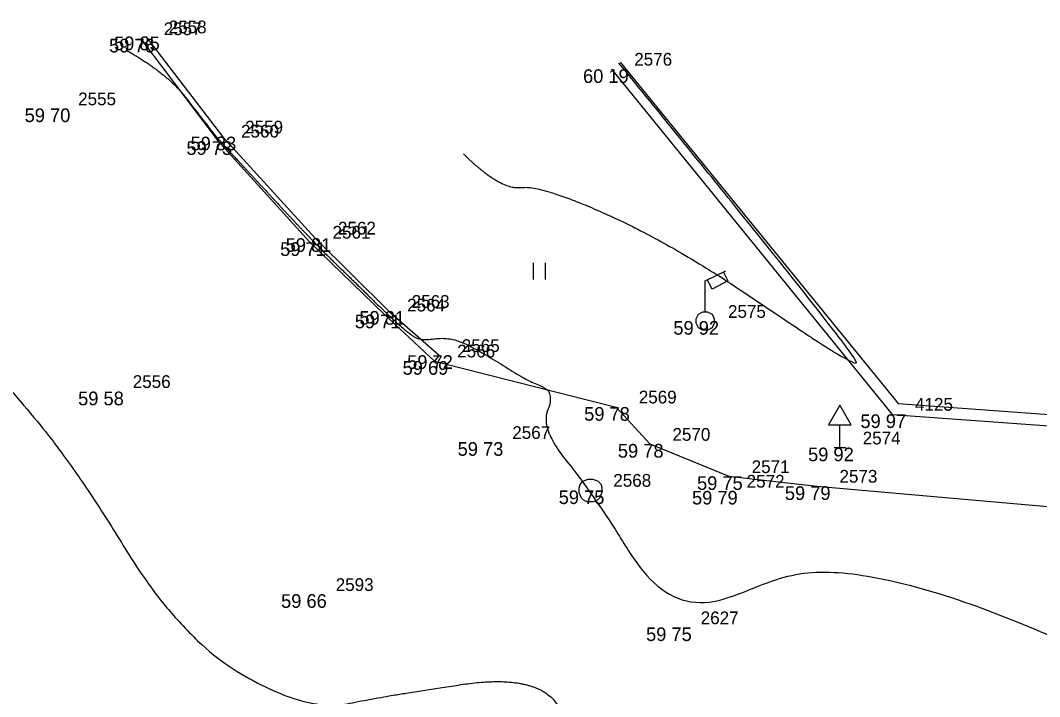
# Model space of a CAD drawing. Extents: x -704017 to -701500, y -1008977 to -1008450.
# Drawn here: x -702593.72 to -702571.32, y -1008762.02 to -1008747.17 of the extents above; entities that cross this region are included whole.
import ezdxf

# ---------------------------------------------------------------- set-up
doc = ezdxf.new("R2010")
doc.units = 0
for name, color, linetype in [('Z_body', 7, 'Continuous'), ('Z_body_cisla', 7, 'Continuous'), ('Z_body_vysky', 7, 'Continuous'), ('Z_dopravni_znaceni', 7, 'Continuous'), ('Z_komunikace', 7, 'Continuous'), ('Z_obruby', 7, 'Continuous'), ('Z_oploceni', 7, 'Continuous'), ('Z_popis', 7, 'Continuous'), ('Z_site_znaky_kanalizace', 7, 'Continuous'), ('Z_site_znaky_VO', 7, 'Continuous'), ('Z_vrstevnice_hlavni', 7, 'Continuous'), ('Z_vrstevnice_vedlejsi', 7, 'Continuous')]:
    doc.layers.add(name, color=color, linetype=linetype)

# ---------------------------------------------------------------- blocks, each defined once
blk = doc.blocks.new('POINT_DISPLAY')
blk.add_line((0, 0), (0, 0))
blk = doc.blocks.new('Z306')
for p, q in [((-0.13, 0.17), (-0.13, -0.2)), ((0.13, 0.17), (0.13, -0.2))]:
    blk.add_line(p, q)
blk = doc.blocks.new('Z13')
for p, q in [((0, 0.88), (0.45, 1.1)), ((0.15, 0.7), (0.05, 0.9)), ((0.4, 1.07), (0.5, 0.88)), ((0, 0.2), (0, 0.88)), ((0.5, 0.88), (0.15, 0.7)), ((-0.2, 0.05), (-0.15, 0.15)), ((-0.2, -0.05), (-0.2, 0.05)), ((-0.15, 0.15), (-0.05, 0.2)), ((-0.05, 0.2), (0.05, 0.2)), ((0.05, 0.2), (0.15, 0.15)), ((0.15, 0.15), (0.2, 0.05)), ((0.2, 0.05), (0.2, -0.05)), ((-0.15, -0.15), (-0.2, -0.05)), ((-0.05, -0.2), (-0.15, -0.15)), ((0.05, -0.2), (-0.05, -0.2)), ((0.15, -0.15), (0.05, -0.2)), ((0.2, -0.05), (0.15, -0.15))]:
    blk.add_line(p, q)
blk = doc.blocks.new('Z527')
for p, q in [((0, 0.93), (-0.25, 0.5)), ((0.25, 0.5), (0, 0.93)), ((-0.25, 0.5), (0.25, 0.5)), ((0, 0), (0, 0.5)), ((-0.13, 0), (0.13, 0))]:
    blk.add_line(p, q)
blk = doc.blocks.new('Z620')
for p, q in [((-0.17, 0.2), (-0.05, 0.25)), ((-0.05, 0.25), (0.05, 0.25)), ((0.05, 0.25), (0.17, 0.2)), ((-0.25, 0.05), (-0.23, 0.13)), ((-0.25, -0.05), (-0.25, 0.05)), ((-0.23, 0.13), (-0.17, 0.2)), ((0.17, 0.2), (0.23, 0.13)), ((0.23, 0.13), (0.25, 0.05)), ((0.25, 0.05), (0.25, -0.05)), ((-0.2, -0.17), (-0.25, -0.05)), ((-0.13, -0.23), (-0.2, -0.17)), ((0.2, -0.17), (0.13, -0.23)), ((0.25, -0.05), (0.2, -0.17)), ((-0.05, -0.25), (-0.13, -0.23)), ((0.05, -0.25), (-0.05, -0.25)), ((0.13, -0.23), (0.05, -0.25))]:
    blk.add_line(p, q)

msp = doc.modelspace()

# ---------------------------------------------------------------- linework, layer by layer
at = {"layer": 'Z_komunikace'}
for p, q in [((-702591.07, -1008747.57), (-702589.37, -1008749.82)), ((-702589.37, -1008749.82), (-702587.36, -1008752.04)), ((-702587.36, -1008752.04), (-702585.72, -1008753.63)), ((-702585.72, -1008753.63), (-702584.62, -1008754.65)), ((-702584.62, -1008754.65), (-702580.63, -1008755.66)), ((-702580.63, -1008755.66), (-702579.89, -1008756.47)), ((-702579.89, -1008756.47), (-702578.15, -1008757.18)), ((-702578.15, -1008757.18), (-702576.22, -1008757.4)), ((-702576.22, -1008757.4), (-702562.62, -1008758.6))]:
    msp.add_line(p, q, dxfattribs=at)
at = {"layer": 'Z_obruby'}
for p, q in [((-702590.96, -1008747.52), (-702589.28, -1008749.72)), ((-702589.28, -1008749.72), (-702587.24, -1008751.95)), ((-702587.24, -1008751.95), (-702585.62, -1008753.55)), ((-702585.62, -1008753.55), (-702584.52, -1008754.52)), ((-702584.52, -1008754.52), (-702584.62, -1008754.65))]:
    msp.add_line(p, q, dxfattribs=at)
at = {"layer": 'Z_oploceni'}
for p, q in [((-702580.54, -1008748.08), (-702574.43, -1008755.58)), ((-702580.73, -1008748.24), (-702574.56, -1008755.82)), ((-702574.43, -1008755.58), (-702561.03, -1008756.56)), ((-702574.56, -1008755.82), (-702561.04, -1008756.81))]:
    msp.add_line(p, q, dxfattribs=at)
at = {"layer": 'Z_vrstevnice_hlavni'}
msp.add_open_spline([(-702583.985, -1008750.095), (-702583.175, -1008750.895), (-702582.262, -1008750.779), (-702579.28, -1008752.131), (-702575.401, -1008754.786), (-702575.289, -1008754.579), (-702580.566, -1008748.102)], degree=2, dxfattribs=at)
at = {"layer": 'Z_vrstevnice_vedlejsi'}
for points in [[(-702591.383, -1008747.825), (-702590.503, -1008748.32), (-702589.635, -1008749.437), (-702589.352, -1008749.8), (-702588.838, -1008750.353), (-702587.312, -1008752.004), (-702586.328, -1008752.958), (-702585.68, -1008753.598), (-702585.12, -1008754.1), (-702584.887, -1008754.197), (-702584.278, -1008754.119), (-702583.643, -1008754.408), (-702582.575, -1008755.09), (-702581.96, -1008755.323), (-702582.298, -1008756.122), (-702581.19, -1008757.49), (-702579.27, -1008760.5), (-702576.041, -1008758.779), (-702569.201, -1008761.361), (-702568.264, -1008762.828), (-702562.973, -1008764.163), (-702556.89, -1008763.701), (-702549.17, -1008761.99), (-702548.2, -1008763.05), (-702545.621, -1008759.916), (-702540.471, -1008758.95), (-702540.495, -1008758.093), (-702535.274, -1008757.786), (-702534.25, -1008757.802), (-702533.983, -1008757.74), (-702533.952, -1008757.707), (-702533.743, -1008757.7)], [(-702608.35, -1008750.923), (-702607.79, -1008750.975), (-702606.949, -1008751.042), (-702606.805, -1008751.216), (-702605.86, -1008752.857), (-702605.496, -1008752.826), (-702605.08, -1008752.838), (-702604.448, -1008752.878), (-702603.894, -1008752.928), (-702603.615, -1008752.962), (-702603.346, -1008755.058), (-702603.088, -1008756.226), (-702602.967, -1008756.819), (-702602.544, -1008756.817), (-702601.956, -1008757.316), (-702597.607, -1008758.681), (-702595.703, -1008760.783), (-702594.812, -1008762.252), (-702593.044, -1008763.271), (-702586.03, -1008765.58), (-702587.969, -1008765.591), (-702589.676, -1008766.526), (-702589.58, -1008766.734)], [(-702601.129, -1008751.002), (-702601.021, -1008751.529), (-702599.508, -1008752.74), (-702599.389, -1008752.863), (-702598.7, -1008752.965), (-702598.085, -1008752.893), (-702597.944, -1008752.878), (-702597.5, -1008752.595), (-702597.064, -1008752.314), (-702597.012, -1008752.255), (-702596.725, -1008751.85), (-702596.461, -1008752.662), (-702595.03, -1008754.083), (-702592.708, -1008756.644), (-702590.225, -1008760.739), (-702587.415, -1008762.358), (-702585.644, -1008761.993), (-702582.355, -1008761.511), (-702581.456, -1008762.92), (-702581.08, -1008763.256), (-702580.688, -1008764.332), (-702579.926, -1008764.63), (-702578.988, -1008764.511), (-702576.482, -1008764.762), (-702576.265, -1008764.772), (-702575.383, -1008764.593), (-702565.138, -1008766.668), (-702565.213, -1008766.698), (-702565.171, -1008766.875), (-702566.987, -1008767.319), (-702567.625, -1008767.989)]]:
    msp.add_open_spline(points, degree=2, dxfattribs=at)

# ---------------------------------------------------------------- block references
at = {"layer": 'Z_body'}
for p in [(-702591.07, -1008747.57), (-702590.96, -1008747.52), (-702580.73, -1008748.24), (-702592.95, -1008749.1), (-702589.28, -1008749.72), (-702589.37, -1008749.82), (-702587.24, -1008751.95), (-702587.36, -1008752.04), (-702585.72, -1008753.63), (-702585.62, -1008753.55), (-702578.67, -1008753.77), (-702584.62, -1008754.65), (-702584.52, -1008754.52), (-702591.75, -1008755.32), (-702580.63, -1008755.66), (-702574.56, -1008755.82), (-702583.41, -1008756.43), (-702579.89, -1008756.47), (-702575.71, -1008756.55), (-702578.15, -1008757.18), (-702581.19, -1008757.49), (-702578.26, -1008757.5), (-702576.22, -1008757.4), (-702587.29, -1008759.77), (-702579.27, -1008760.5)]:
    msp.add_blockref('POINT_DISPLAY', p, dxfattribs=at)
at = {"layer": 'Z_dopravni_znaceni'}
msp.add_blockref('Z527', (-702575.71, -1008756.55), dxfattribs=at)
at = {"layer": 'Z_popis'}
msp.add_blockref('Z306', (-702582.32, -1008752.66), dxfattribs=at)
at = {"layer": 'Z_site_znaky_kanalizace'}
msp.add_blockref('Z620', (-702581.19, -1008757.49), dxfattribs=at)
at = {"layer": 'Z_site_znaky_VO'}
msp.add_blockref('Z13', (-702578.67, -1008753.77), dxfattribs=at)

# ---------------------------------------------------------------- texts
at = {"layer": 'Z_body_cisla'}
for s, p in [('2557', (-702590.57, -1008747.49)), ('2558', (-702590.46, -1008747.45)), ('2576', (-702580.23, -1008748.16)), ('2555', (-702592.45, -1008749.03)), ('2560', (-702588.87, -1008749.74)), ('2559', (-702588.78, -1008749.65)), ('2561', (-702586.86, -1008751.96)), ('2562', (-702586.74, -1008751.87)), ('2564', (-702585.22, -1008753.56)), ('2563', (-702585.12, -1008753.48)), ('2575', (-702578.17, -1008753.7)), ('2565', (-702584.02, -1008754.45)), ('2566', (-702584.12, -1008754.57)), ('2556', (-702591.25, -1008755.24)), ('2569', (-702580.13, -1008755.58)), ('4125', (-702574.06, -1008755.74)), ('2567', (-702582.91, -1008756.36)), ('2570', (-702579.39, -1008756.4)), ('2574', (-702575.21, -1008756.48)), ('2571', (-702577.65, -1008757.11)), ('2568', (-702580.69, -1008757.41)), ('2573', (-702575.72, -1008757.32)), ('2572', (-702577.76, -1008757.43)), ('2593', (-702586.79, -1008759.7)), ('2627', (-702578.77, -1008760.43))]:
    msp.add_text(s, height=0.28, dxfattribs=at).set_placement(p)
at = {"layer": 'Z_body_vysky'}
for s, p in [('59 76', (-702591.77, -1008747.87)), ('59 85', (-702591.66, -1008747.82)), ('60 19', (-702581.355, -1008748.54)), ('59 70', (-702593.625, -1008749.4)), ('59 83', (-702589.98, -1008750.02)), ('59 73', (-702590.07, -1008750.12)), ('59 81', (-702587.89, -1008752.25)), ('59 71', (-702588.01, -1008752.34)), ('59 71', (-702586.37, -1008753.93)), ('59 81', (-702586.27, -1008753.85)), ('59 92', (-702579.37, -1008754.07)), ('59 69', (-702585.32, -1008754.95)), ('59 72', (-702585.22, -1008754.82)), ('59 58', (-702592.45, -1008755.62)), ('59 78', (-702581.33, -1008755.96)), ('59 97', (-702575.26, -1008756.12)), ('59 73', (-702584.11, -1008756.73)), ('59 78', (-702580.59, -1008756.77)), ('59 92', (-702576.41, -1008756.85)), ('59 75', (-702578.85, -1008757.48)), ('59 75', (-702581.89, -1008757.79)), ('59 79', (-702578.96, -1008757.8)), ('59 79', (-702576.92, -1008757.7)), ('59 66', (-702587.99, -1008760.07)), ('59 75', (-702579.97, -1008760.8))]:
    msp.add_text(s, height=0.3, dxfattribs=at).set_placement(p)

doc.saveas('drawing.dxf')
